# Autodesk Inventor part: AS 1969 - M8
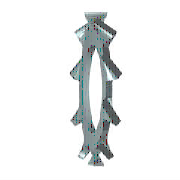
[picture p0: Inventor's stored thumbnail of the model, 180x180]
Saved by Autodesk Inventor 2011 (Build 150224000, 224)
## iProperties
IsCustomPart: 0
Created: 2008-02
Part Number: AS 1969 - M8
Material: Steel, Mild
Description: Metric Tooth LW
Document SubType Name: Modeling
Standard: AS 1969
Designer: PN
Standards Organization: AS
Language: en-US
Size Designation: M8
Categories: <MemberInstance><Categories><Category DisplayName="Fasteners" InternalName="e4da775c-781d-43d5-af7c-5136215cf5a6" Mnemonic="FSTN"><Category DisplayName="Washers
Density: 7.86 g/cm^3
Mass: 0.474048 g
Surface Area: 2.15852 cm^2
Volume: 0.0603114 cm^3
Author: PN
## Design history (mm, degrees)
pattern_circular "Cuts" dims angle "d11" = 360 deg
sketch "Sketch1"
  geometry: C1 r 7 at (0, 0); C2 r 4.2 at (0, 0)
  constraints: 2 centre point, 1 coincident, 1 other
  dimensions: "d0" = 14 diameter of C1 (= SD2); "d1" = 8.4 diameter of C2 (= SD1)
extrude "Body" new body sketch "Sketch1" distance "d2" = 0.85 (= SD); taper "d3" = 0 deg
sketch "Sketch2"
  geometry: L1 (0, 0)-(0, 7); L2 (-1.093, 5.492)-(-1.366, 6.865); L3 (1.093, 5.492)-(1.366, 6.865); L4 (-1.093, 5.492)-(0, 0); L5 (0, 0)-(1.093, 5.492); A1 r 7 centre (0, 0) between (0, 7) and (1.366, 6.865) reference; A2 r 7 centre (0, 0) between (1.366, 6.865) and (-1.366, 6.865); A3 r 5.6 centre (0, 0) between (1.093, 5.492) and (-1.093, 5.492)
  constraints: 10 end point, 7 point on circle, 2 centre point, 2 coincident, 2 collinear, 1 concentric, 1 symmetric about line, 1 vertical
  dimensions: "d4" = 22.5 deg angle of L3 L2 (computed from SAZ); "d5" = 11.2 diameter of A3 (= 0.5 x SD2 + 0.5 x SD1)
extrude "Cut" cut sketch "Sketch2" stored distance "d6" = 0.85 (= SD); taper "d7" = 0 deg
workaxis "Work Axis1"
workplane "Work Plane1"
body "Solid1"
fillet "Fillet1" dims "d8" = 0.21 (= 0.015 x SD2)
other parameters: "SD" = 0.85 [user parameter; used in 2 equation terms], "SD1" = 8.4 [user parameter; used in 2 equation terms], "SD2" = 14 [user parameter; used in 3 equation terms], "NND" = 8 [user parameter], "d12" = 0, "d13" = 0, "d14" = 0, "d15" = 0, "d16" = 90 deg
